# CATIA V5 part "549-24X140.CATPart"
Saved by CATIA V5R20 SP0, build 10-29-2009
Part number: 549-24X140
Definition: NONE
Nomenclature: 549-24X140
Source: Unknown
Description: 549-24X140
Bounding box of the stored display mesh (mm): x 0 to 140, y -13.5 to 13.5, z -13.5 to 13.5
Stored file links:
  C:\Users\Utente\Desktop\IO LAVORO\3D X SITO CF\X SITO\PLASTICA\549\549-24X140.CATPart
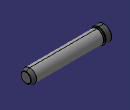
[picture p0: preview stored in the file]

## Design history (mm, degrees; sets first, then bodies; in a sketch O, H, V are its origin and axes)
Body1 "549-24X140" (main body)
  Solid1: solid without history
